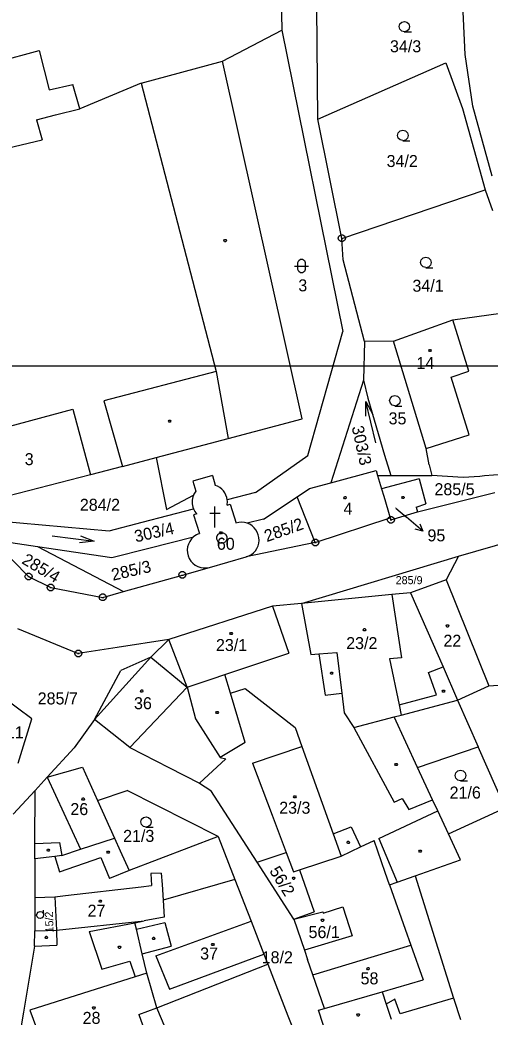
# Model space of a CAD drawing. Extents: x -780000 to -777378, y -1011169 to -1009297.
# Drawn here: x -779169.3 to -779102.6, y -1010360.1 to -1010218.8 of the extents above; entities that cross this region are included whole.
import ezdxf

# ---------------------------------------------------------------- set-up
doc = ezdxf.new("R2010")
doc.units = 0
for name, color, linetype in [('Default', 7, 'Continuous'), ('KN_HRANICE', 7, 'Continuous'), ('KN_KULTURY', 7, 'Continuous'), ('KN_PARCELY', 7, 'Continuous'), ('KN_SLUCKY', 7, 'Continuous'), ('LEGENDA', 7, 'Continuous')]:
    doc.layers.add(name, color=color, linetype=linetype)

# ---------------------------------------------------------------- blocks, each defined once
blk = doc.blocks.new('101')
at = {"layer": 'Default'}
blk.add_line((-0.05, 0), (0.05, 0), dxfattribs=at)
blk.add_lwpolyline([(0.19, 0.72), (0.53, 0.53), (0.72, 0.19), (0.72, -0.2), (0.53, -0.54), (0.19, -0.73), (-0.2, -0.73), (-0.54, -0.54), (-0.73, -0.2), (-0.73, 0.19), (-0.54, 0.53), (-0.2, 0.72), (0.19, 0.72)], dxfattribs=at)
blk = doc.blocks.new('304')
at = {"layer": 'Default'}
blk.add_lwpolyline([(0, 0), (-0.38, 0.1), (-0.65, 0.37), (-0.75, 0.74), (-0.65, 1.11), (-0.38, 1.38), (-0.01, 1.48), (0.36, 1.38), (0.63, 1.11), (0.73, 0.73), (0.63, 0.35), (0.36, 0.08), (-0.02, -0.02), (0.98, -0.02)], dxfattribs=at)
blk = doc.blocks.new('316')
at = {"layer": 'Default'}
for points in [[(-0.5, 1.5), (-0.4, 1.79), (-0.15, 1.97), (0.16, 1.97), (0.41, 1.79), (0.51, 1.5), (0.51, 0.5), (0.41, 0.21), (0.16, 0.03), (-0.15, 0.03), (-0.4, 0.21), (-0.5, 0.5), (-0.5, 1.5)], [(-1, 1), (0.27, 1), (1, 1)]]:
    blk.add_lwpolyline(points, dxfattribs=at)
blk = doc.blocks.new('NAHRADNI_SYMBOL')
at = {"layer": 'Default'}
blk.add_lwpolyline([(0.09, 0.15), (0.18, 0), (0.09, -0.15), (-0.09, -0.15), (-0.18, 0), (-0.09, 0.15), (0.09, 0.15)], dxfattribs=at)
blk = doc.blocks.new('802')
at = {"layer": 'Default'}
blk.add_line((-3, 0), (3, 0), dxfattribs=at)
blk.add_lwpolyline([(1, 0.5), (3, 0), (1, -0.5)], dxfattribs=at)
blk = doc.blocks.new('10292')
at = {"layer": 'Default'}
blk.add_line((0, 3), (0, 0), dxfattribs=at)
blk.add_lwpolyline([(-0.5, 2), (0, 3), (0.5, 2)], dxfattribs=at)
blk = doc.blocks.new('402')
at = {"layer": 'Default'}
blk.add_lwpolyline([(0.09, 0.15), (0.18, 0), (0.09, -0.15), (-0.09, -0.15), (-0.18, 0), (-0.09, 0.15), (0.09, 0.15)], dxfattribs=at)
blk = doc.blocks.new('4091')
at = {"layer": 'Default'}
for p, q in [((0, 0), (0, 3)), ((0.75, 2), (-0.75, 2))]:
    blk.add_line(p, q, dxfattribs=at)
blk = doc.blocks.new('105')
at = {"layer": 'Default'}
blk.add_line((-0.12, 0), (0.12, 0), dxfattribs=at)
blk.add_lwpolyline([(0.15, 0.48), (0.4, 0.3), (0.5, 0.01), (0.4, -0.28), (0.15, -0.46), (-0.16, -0.46), (-0.41, -0.28), (-0.51, 0.01), (-0.41, 0.3), (-0.16, 0.48), (0.15, 0.48)], dxfattribs=at)

msp = doc.modelspace()

# ---------------------------------------------------------------- linework, layer by layer
at = {"layer": 'KN_HRANICE'}
for p, q in [((-779132.76, -1010196.68), (-779132.14, -1010220.3)), ((-779106.16, -1010223.74), (-779106.91, -1010208.39)), ((-779127.06, -1010232.92), (-779127.2, -1010217)), ((-779140.53, -1010224.66), (-779132.14, -1010220.3)), ((-779132.14, -1010220.3), (-779123.49, -1010263.01)), ((-779185.42, -1010228.21), (-779166.52, -1010223.19)), ((-779166.52, -1010223.19), (-779165.11, -1010228.72)), ((-779105.07, -1010231.05), (-779106.16, -1010223.74)), ((-779152.1, -1010227.79), (-779140.53, -1010224.66)), ((-779129.26, -1010275.39), (-779140.53, -1010224.66)), ((-779127.06, -1010232.92), (-779108.9, -1010224.93)), ((-779108.9, -1010224.93), (-779106.53, -1010231.41)), ((-779165.11, -1010228.72), (-779161.77, -1010228)), ((-779160.79, -1010231.43), (-779161.77, -1010228)), ((-779152.1, -1010227.79), (-779160.79, -1010231.43)), ((-779102.33, -1010241), (-779105.07, -1010231.05)), ((-779106.53, -1010231.41), (-779103.32, -1010242.93)), ((-779123.64, -1010249.79), (-779127.06, -1010232.92)), ((-779123.64, -1010249.79), (-779103.32, -1010242.93)), ((-779103.32, -1010242.93), (-779102.28, -1010245.85)), ((-779123.44, -1010252.85), (-779123.64, -1010249.79)), ((-779120.42, -1010264.41), (-779123.44, -1010252.85)), ((-779107.93, -1010261.36), (-779101.09, -1010260.41)), ((-779116.32, -1010264.37), (-779107.93, -1010261.36)), ((-779128.47, -1010280.58), (-779123.49, -1010263.01)), ((-779120.42, -1010264.41), (-779120.56, -1010269.87)), ((-779116.32, -1010264.37), (-779120.42, -1010264.41)), ((-779111.69, -1010279.58), (-779116.32, -1010264.37)), ((-779120.56, -1010269.87), (-779125.19, -1010284.44)), ((-779120.56, -1010269.87), (-779119.96, -1010272.44)), ((-779119.96, -1010272.44), (-779117.61, -1010280.51)), ((-779139.76, -1010278.16), (-779129.26, -1010275.39)), ((-779149.94, -1010280.84), (-779139.76, -1010278.16)), ((-779135.87, -1010285.81), (-779128.47, -1010280.58)), ((-779117.61, -1010280.51), (-779116.7, -1010283.39)), ((-779111.28, -1010281.87), (-779111.69, -1010279.58)), ((-779154.7, -1010282.1), (-779159.28, -1010283.29)), ((-779154.7, -1010282.1), (-779149.94, -1010280.84)), ((-779149.94, -1010280.84), (-779148.5, -1010288.21)), ((-779111.28, -1010281.87), (-779110.91, -1010283.41)), ((-779159.28, -1010283.29), (-779177.62, -1010288.07)), ((-779141.98, -1010283.41), (-779144.76, -1010284.21)), ((-779141.98, -1010283.41), (-779141.57, -1010284.79)), ((-779125.19, -1010284.44), (-779118.78, -1010282.71)), ((-779118.78, -1010282.71), (-779118.58, -1010283.38)), ((-779118.58, -1010283.38), (-779116.7, -1010283.39)), ((-779118.58, -1010283.38), (-779118.01, -1010285.29)), ((-779116.7, -1010283.39), (-779110.91, -1010283.41)), ((-779106.44, -1010283.7), (-779110.91, -1010283.41)), ((-779144.76, -1010284.21), (-779144.33, -1010285.63)), ((-779128.24, -1010285.26), (-779125.19, -1010284.44)), ((-779112.67, -1010283.87), (-779118.01, -1010285.29)), ((-779112.67, -1010283.87), (-779111.73, -1010287.42)), ((-779148.5, -1010288.21), (-779144.67, -1010286.2)), ((-779135.87, -1010285.81), (-779139.88, -1010286.86)), ((-779129.95, -1010286.4), (-779128.24, -1010285.26)), ((-779118.01, -1010285.29), (-779117.7, -1010286.32)), ((-779117.7, -1010286.32), (-779116.78, -1010289.39)), ((-779112.94, -1010288.54), (-779101.94, -1010285.82)), ((-779139.9, -1010287.6), (-779139.45, -1010287.47)), ((-779139.45, -1010287.47), (-779138.64, -1010290.15)), ((-779134.73, -1010289.57), (-779129.95, -1010286.4)), ((-779127.4, -1010292.89), (-779129.95, -1010286.4)), ((-779113.12, -1010287.88), (-779111.73, -1010287.42)), ((-779151.93, -1010290), (-779144.67, -1010288.11)), ((-779144.21, -1010288.84), (-779144.64, -1010288.96)), ((-779144.64, -1010288.96), (-779143.83, -1010291.64)), ((-779116.69, -1010289.7), (-779112.94, -1010288.54)), ((-779113.12, -1010287.88), (-779112.94, -1010288.54)), ((-779176.23, -1010289.47), (-779156.62, -1010291.23)), ((-779156.62, -1010291.23), (-779151.93, -1010290)), ((-779134.73, -1010289.57), (-779137.06, -1010290.16)), ((-779127.4, -1010292.89), (-779116.78, -1010289.39)), ((-779116.78, -1010289.39), (-779116.69, -1010289.7)), ((-779173.19, -1010292.52), (-779168.03, -1010297.71)), ((-779173.19, -1010292.52), (-779166.79, -1010293.46)), ((-779150.97, -1010293.68), (-779144.65, -1010292.08)), ((-779127.4, -1010292.89), (-779137.19, -1010294.93)), ((-779107.13, -1010294.85), (-779097.5, -1010292.06)), ((-779166.79, -1010293.46), (-779156.22, -1010295.01)), ((-779166.79, -1010293.46), (-779154.6, -1010299.85)), ((-779156.22, -1010295.01), (-779150.97, -1010293.68)), ((-779129.38, -1010301.54), (-779107.13, -1010294.85)), ((-779107.13, -1010294.85), (-779108.85, -1010298.16)), ((-779142.38, -1010296.42), (-779137.19, -1010294.93)), ((-779154.6, -1010299.85), (-779146.24, -1010297.5)), ((-779146.24, -1010297.5), (-779142.38, -1010296.42)), ((-779168.03, -1010297.71), (-779164.89, -1010299.28)), ((-779108.85, -1010298.16), (-779113.91, -1010300.03)), ((-779164.89, -1010299.28), (-779157.51, -1010300.67)), ((-779157.51, -1010300.67), (-779154.6, -1010299.85)), ((-779116.55, -1010300.26), (-779129.38, -1010301.54)), ((-779113.91, -1010300.03), (-779116.55, -1010300.26)), ((-779113.91, -1010300.03), (-779109.3, -1010310.52)), ((-779133.45, -1010301.92), (-779148.16, -1010306.65)), ((-779129.38, -1010301.54), (-779133.45, -1010301.92)), ((-779129.38, -1010301.54), (-779128.03, -1010308.75)), ((-779169.61, -1010305.1), (-779160.99, -1010308.63)), ((-779150.7, -1010309.16), (-779148.16, -1010306.65)), ((-779145.58, -1010313.4), (-779148.16, -1010306.65)), ((-779128.03, -1010308.75), (-779126.89, -1010308.67)), ((-779126.89, -1010308.67), (-779124.34, -1010308.48)), ((-779124.34, -1010308.48), (-779123.62, -1010314.23)), ((-779150.7, -1010309.16), (-779154.94, -1010311.03)), ((-779158.7, -1010317.98), (-779154.94, -1010311.03)), ((-779142.02, -1010312.21), (-779140.22, -1010311.61)), ((-779139.43, -1010314.26), (-779140.22, -1010311.61)), ((-779109.3, -1010310.52), (-779107.24, -1010315.22)), ((-779145.58, -1010313.4), (-779142.02, -1010312.21)), ((-779107.24, -1010315.22), (-779102.83, -1010313.22)), ((-779102.83, -1010313.22), (-779096.1, -1010312.69)), ((-779145.58, -1010313.4), (-779144.39, -1010317.86)), ((-779139.43, -1010314.26), (-779137.34, -1010313.6)), ((-779137.34, -1010313.6), (-779130.26, -1010319.11)), ((-779123.62, -1010314.23), (-779123.32, -1010317.03)), ((-779167.55, -1010317.87), (-779171.61, -1010314.85)), ((-779107.24, -1010315.22), (-779104.32, -1010321.87)), ((-779123.32, -1010317.03), (-779121.94, -1010319.13)), ((-779169.49, -1010324.18), (-779167.55, -1010317.87)), ((-779158.7, -1010317.98), (-779161.56, -1010321.97)), ((-779153.68, -1010321.94), (-779158.7, -1010317.98)), ((-779144.39, -1010317.86), (-779140.88, -1010323.34)), ((-779121.94, -1010319.13), (-779116.23, -1010317.61)), ((-779112.91, -1010324.76), (-779116.23, -1010317.61)), ((-779130.26, -1010319.11), (-779129.3, -1010321.78)), ((-779165.4, -1010326.16), (-779161.56, -1010321.97)), ((-779153.68, -1010321.94), (-779148.16, -1010324.76)), ((-779129.3, -1010321.78), (-779124.85, -1010334.2)), ((-779112.91, -1010324.76), (-779104.32, -1010321.87)), ((-779100.48, -1010330.51), (-779104.32, -1010321.87)), ((-779143.8, -1010326.98), (-779140.06, -1010323.57)), ((-779140.88, -1010323.34), (-779140.06, -1010323.57)), ((-779165.4, -1010326.16), (-779160.41, -1010324.71)), ((-779160.41, -1010324.71), (-779158.26, -1010329.46)), ((-779148.16, -1010324.76), (-779143.8, -1010326.98)), ((-779110.78, -1010329.34), (-779112.91, -1010324.76)), ((-779167.12, -1010328.04), (-779165.4, -1010326.16)), ((-779143.8, -1010326.98), (-779142.22, -1010328.02)), ((-779170.22, -1010331.41), (-779167.12, -1010328.04)), ((-779167.14, -1010335.56), (-779167.12, -1010328.04)), ((-779158.26, -1010329.46), (-779154.05, -1010328.04)), ((-779141.16, -1010334.55), (-779154.05, -1010328.04)), ((-779135.65, -1010338.2), (-779142.22, -1010328.02)), ((-779158.26, -1010329.46), (-779155.86, -1010334.78)), ((-779110.04, -1010330.92), (-779110.78, -1010329.34)), ((-779108.53, -1010334.17), (-779110.04, -1010330.92)), ((-779108.53, -1010334.17), (-779100.48, -1010330.51)), ((-779124.85, -1010334.2), (-779123.73, -1010337.33)), ((-779106.82, -1010337.84), (-779108.53, -1010334.17)), ((-779167.14, -1010337.72), (-779167.14, -1010335.56)), ((-779160.66, -1010336.36), (-779155.86, -1010334.78)), ((-779155.86, -1010334.78), (-779155.05, -1010336.58)), ((-779141.16, -1010334.55), (-779153.78, -1010339.39)), ((-779141.16, -1010334.55), (-779138.79, -1010340.66)), ((-779120.99, -1010336.04), (-779119.07, -1010335.14)), ((-779117.5, -1010339.64), (-779119.07, -1010335.14)), ((-779163.3, -1010337.23), (-779164.32, -1010337.41)), ((-779163.3, -1010337.23), (-779160.66, -1010336.36)), ((-779155.05, -1010336.58), (-779153.78, -1010339.39)), ((-779135.65, -1010338.2), (-779131.51, -1010336.82)), ((-779131.51, -1010336.82), (-779130.47, -1010339.58)), ((-779123.73, -1010337.33), (-779120.99, -1010336.04)), ((-779167.14, -1010337.72), (-779167.15, -1010343.18)), ((-779164.32, -1010337.41), (-779167.14, -1010337.72)), ((-779130.45, -1010346.25), (-779135.65, -1010338.2)), ((-779129.62, -1010339.3), (-779123.73, -1010337.33)), ((-779113.27, -1010340.13), (-779106.82, -1010337.84)), ((-779130.47, -1010339.58), (-779129.62, -1010339.3)), ((-779129.62, -1010339.3), (-779127.57, -1010345.23)), ((-779116.88, -1010341.42), (-779117.5, -1010339.64)), ((-779138.79, -1010340.66), (-779148.98, -1010343.57)), ((-779138.79, -1010340.66), (-779136.5, -1010346.55)), ((-779116.88, -1010341.42), (-779115.81, -1010341.04)), ((-779116.88, -1010341.42), (-779114.67, -1010347.67)), ((-779115.81, -1010341.04), (-779113.27, -1010340.13)), ((-779113.27, -1010340.13), (-779107.81, -1010357.49)), ((-779167.15, -1010343.18), (-779167.16, -1010347.93)), ((-779167.15, -1010343.18), (-779164.31, -1010343.12)), ((-779164.31, -1010343.12), (-779164.08, -1010347.83)), ((-779148.98, -1010343.57), (-779148.82, -1010345.98)), ((-779130.45, -1010346.25), (-779127.57, -1010345.23)), ((-779164.08, -1010347.83), (-779151.66, -1010346.5)), ((-779152.96, -1010346.81), (-779151.66, -1010346.5)), ((-779152.75, -1010347.71), (-779152.96, -1010346.81)), ((-779148.82, -1010345.98), (-779151.66, -1010346.5)), ((-779136.5, -1010346.55), (-779134.69, -1010351.21)), ((-779130.45, -1010346.25), (-779128.94, -1010350.68)), ((-779167.17, -1010350.08), (-779167.16, -1010347.93)), ((-779167.16, -1010347.93), (-779164.08, -1010347.83)), ((-779151.93, -1010351.2), (-779152.75, -1010347.71)), ((-779114.67, -1010347.67), (-779113.87, -1010349.95)), ((-779127.75, -1010354.15), (-779113.87, -1010349.95)), ((-779167.17, -1010350.08), (-779168.77, -1010359.47)), ((-779151.29, -1010353.93), (-779151.93, -1010351.2)), ((-779134.69, -1010351.21), (-779134.14, -1010352.63)), ((-779128.94, -1010350.68), (-779128.49, -1010351.99)), ((-779149.85, -1010358.82), (-779134.14, -1010352.63)), ((-779134.14, -1010352.63), (-779131.3, -1010359.95)), ((-779127.75, -1010354.15), (-779128.49, -1010351.99)), ((-779149.85, -1010358.82), (-779151.29, -1010353.93)), ((-779126.12, -1010358.95), (-779127.75, -1010354.15)), ((-779126.12, -1010358.95), (-779117.94, -1010356.58)), ((-779117.94, -1010356.58), (-779117.35, -1010358.34)), ((-779117.35, -1010358.34), (-779116.64, -1010360.46)), ((-779107.81, -1010357.49), (-779107.71, -1010357.68)), ((-779106.8, -1010360.53), (-779107.71, -1010357.68)), ((-779168.77, -1010359.47), (-779169.76, -1010365.24)), ((-779148.14, -1010362.87), (-779149.85, -1010358.82)), ((-779126.93, -1010359.19), (-779126.12, -1010358.95)), ((-779124.81, -1010365.65), (-779126.93, -1010359.19)), ((-779131.3, -1010359.95), (-779128.72, -1010366.32))]:
    msp.add_line(p, q, dxfattribs=at)
for points in [[(-779097.04, -1010282.96), (-779103.42, -1010283.46), (-779104.11, -1010283.52), (-779106.44, -1010283.7)], [(-779148.16, -1010306.65), (-779155.46, -1010307.78), (-779160.99, -1010308.63)], [(-779107.81, -1010357.49), (-779115.4, -1010359.69), (-779116.13, -1010357.63), (-779117.35, -1010358.34)]]:
    msp.add_lwpolyline(points, dxfattribs=at)
for centre, radius, start, end in [((-779142.38, -1010287.18), 2.52, 7.2029, 71.2552), ((-779142.41, -1010287.15), 2.45, 157.0664, 202.9336), ((-779142.11, -1010287.34), 2.8, 142.3745, 155.9941), ((-779142.16, -1010287.17), 2.3, 349.1876, 7.7161), ((-779142.3, -1010287.13), 2.56, 202.5278, 221.9053), ((-779137.87, -1010292.59), 2.56, 71.6556, 107.6192), ((-779137.87, -1010292.52), 2.5, 285.7463, 71.1314), ((-779142.99, -1010294.19), 2.68, 108.2322, 128.2025), ((-779143.03, -1010294), 2.51, 130.2372, 284.9856)]:
    msp.add_arc(centre, radius, start, end, dxfattribs=at)
at = {"layer": 'KN_PARCELY'}
msp.add_line((-779116, -1010288.01), (-779114.46, -1010289.32), dxfattribs=at)
at = {"layer": 'KN_SLUCKY'}
for p, q in [((-779152.1, -1010227.79), (-779141.46, -1010268.66)), ((-779166.93, -1010233.01), (-779164.21, -1010232.28)), ((-779164.21, -1010232.28), (-779160.79, -1010231.43)), ((-779166.93, -1010233.01), (-779166.12, -1010235.81)), ((-779171.09, -1010237.01), (-779166.12, -1010235.81)), ((-779105.66, -1010268.59), (-779107.93, -1010261.36)), ((-779141.46, -1010268.66), (-779157.38, -1010272.82)), ((-779141.46, -1010268.66), (-779139.76, -1010278.16)), ((-779108.14, -1010269.47), (-779105.66, -1010268.59)), ((-779105.62, -1010277.63), (-779108.14, -1010269.47)), ((-779157.38, -1010272.82), (-779154.7, -1010282.1)), ((-779178.75, -1010278.56), (-779161.78, -1010273.99)), ((-779161.78, -1010273.99), (-779159.28, -1010283.29)), ((-779111.69, -1010279.58), (-779105.62, -1010277.63)), ((-779108.85, -1010298.16), (-779102.83, -1010313.22)), ((-779116.55, -1010300.26), (-779115.17, -1010309.24)), ((-779133.45, -1010301.92), (-779131.16, -1010308.58)), ((-779140.22, -1010311.61), (-779131.16, -1010308.58)), ((-779126.89, -1010308.67), (-779126, -1010314.52)), ((-779158.7, -1010317.98), (-779150.7, -1010309.16)), ((-779150.7, -1010309.16), (-779145.58, -1010313.4)), ((-779115.17, -1010309.24), (-779116.88, -1010309.36)), ((-779116.88, -1010309.36), (-779115.53, -1010315.91)), ((-779111.38, -1010311.33), (-779109.3, -1010310.52)), ((-779110.21, -1010314.47), (-779111.38, -1010311.33)), ((-779153.68, -1010321.94), (-779145.58, -1010313.4)), ((-779137.35, -1010321.23), (-779139.43, -1010314.26)), ((-779126, -1010314.52), (-779123.62, -1010314.23)), ((-779115.53, -1010315.91), (-779110.21, -1010314.47)), ((-779115.53, -1010315.91), (-779115.23, -1010317.34)), ((-779115.23, -1010317.34), (-779107.24, -1010315.22)), ((-779116.23, -1010317.61), (-779115.23, -1010317.34)), ((-779121.94, -1010319.13), (-779116.22, -1010329.71)), ((-779137.35, -1010321.23), (-779140.88, -1010323.34)), ((-779136.29, -1010324.15), (-779129.3, -1010321.78)), ((-779136.29, -1010324.15), (-779133.52, -1010331.51)), ((-779165.4, -1010326.16), (-779160.66, -1010336.36)), ((-779116.22, -1010329.71), (-779115.11, -1010329.15)), ((-779115.11, -1010329.15), (-779114.16, -1010330.74)), ((-779114.16, -1010330.74), (-779110.78, -1010329.34)), ((-779133.52, -1010331.51), (-779131.51, -1010336.82)), ((-779118.38, -1010334.82), (-779110.04, -1010330.92)), ((-779124.85, -1010334.2), (-779122.33, -1010333.18)), ((-779122.33, -1010333.18), (-779120.99, -1010336.04)), ((-779167.14, -1010335.56), (-779163.63, -1010335.4)), ((-779163.63, -1010335.4), (-779163.3, -1010337.23)), ((-779118.38, -1010334.82), (-779115.81, -1010341.04)), ((-779164.32, -1010337.41), (-779163.63, -1010339.56)), ((-779163.63, -1010339.56), (-779157.78, -1010337.53)), ((-779157.78, -1010337.53), (-779156.56, -1010340.49)), ((-779153.78, -1010339.39), (-779156.56, -1010340.49)), ((-779149.23, -1010339.75), (-779150.73, -1010339.81)), ((-779150.73, -1010339.81), (-779150.61, -1010341.52)), ((-779149.23, -1010339.75), (-779149.12, -1010341.37)), ((-779149.12, -1010341.37), (-779148.98, -1010343.57)), ((-779162.78, -1010342.94), (-779152.1, -1010341.68)), ((-779152.1, -1010341.68), (-779150.61, -1010341.52)), ((-779164.31, -1010343.12), (-779162.78, -1010342.94)), ((-779130.45, -1010346.25), (-779126.34, -1010345.23)), ((-779126.34, -1010345.23), (-779126.27, -1010345.4)), ((-779126.27, -1010345.4), (-779123.51, -1010344.52)), ((-779123.51, -1010344.52), (-779122.2, -1010348.62)), ((-779159.47, -1010348.01), (-779152.96, -1010346.81)), ((-779152.75, -1010347.71), (-779148.71, -1010346.75)), ((-779149.98, -1010351.45), (-779136.5, -1010346.55)), ((-779148.71, -1010346.75), (-779147.85, -1010350.1)), ((-779164.08, -1010347.83), (-779164.04, -1010349.95)), ((-779159.47, -1010348.01), (-779157.66, -1010353.36)), ((-779167.17, -1010350.08), (-779164.04, -1010349.95)), ((-779122.2, -1010348.62), (-779128.94, -1010350.68)), ((-779113.87, -1010349.95), (-779112.12, -1010354.89)), ((-779151.93, -1010351.2), (-779147.85, -1010350.1)), ((-779148.04, -1010356.21), (-779134.69, -1010351.21)), ((-779157.66, -1010353.36), (-779153.67, -1010352.23)), ((-779153.67, -1010352.23), (-779152.93, -1010354.43)), ((-779149.98, -1010351.45), (-779148.04, -1010356.21)), ((-779151.29, -1010353.93), (-779152.93, -1010354.43)), ((-779152.93, -1010354.43), (-779167.87, -1010359.19)), ((-779117.94, -1010356.58), (-779112.12, -1010354.89)), ((-779167.87, -1010359.19), (-779166.01, -1010364.05)), ((-779152.41, -1010359.76), (-779149.85, -1010358.82)), ((-779152.41, -1010359.76), (-779150.92, -1010363.88))]:
    msp.add_line(p, q, dxfattribs=at)
at = {"layer": 'LEGENDA'}
msp.add_lwpolyline([(-779530.66, -1010687.91), (-778936.66, -1010687.91), (-778936.66, -1010267.91), (-779530.66, -1010267.91)], close=True, dxfattribs=at)

# ---------------------------------------------------------------- block references
at = {"layer": 'KN_KULTURY'}
for name, p in [('304', (-779114.77, -1010220.52)), ('304', (-779114.99, -1010235.94)), ('402', (-779140.18, -1010250.11)), ('304', (-779111.73, -1010253.93)), ('316', (-779129.36, -1010254.72)), ('402', (-779111.15, -1010265.67)), ('304', (-779116.12, -1010273.53)), ('402', (-779148.04, -1010275.71)), ('402', (-779123.19, -1010286.54)), ('NAHRADNI_SYMBOL', (-779114.97, -1010286.53)), ('4091', (-779141.62, -1010290.77)), ('402', (-779140.79, -1010291.53)), ('402', (-779108.68, -1010304.72)), ('402', (-779139.32, -1010305.78)), ('402', (-779120.43, -1010305.25)), ('402', (-779125.09, -1010311.42)), ('402', (-779152, -1010313.94)), ('402', (-779109.24, -1010313.97)), ('402', (-779141.32, -1010316.99)), ('402', (-779115.94, -1010324.35)), ('304', (-779106.82, -1010326.65)), ('402', (-779130.3, -1010328.92)), ('402', (-779160.31, -1010329.25)), ('304', (-779151.38, -1010333.23)), ('402', (-779122.73, -1010335.39)), ('402', (-779165.24, -1010336.5)), ('402', (-779156.75, -1010336.78)), ('402', (-779112.55, -1010336.62)), ('402', (-779130.47, -1010340.48)), ('402', (-779157.87, -1010343.72)), ('402', (-779126.38, -1010346.43)), ('402', (-779165.52, -1010348.85)), ('402', (-779150.31, -1010348.99)), ('402', (-779141.92, -1010349.85)), ('402', (-779155.14, -1010350.26)), ('402', (-779119.93, -1010353.29)), ('402', (-779158.8, -1010358.86)), ('402', (-779121.32, -1010359.85))]:
    msp.add_blockref(name, p, dxfattribs=at)
for p, rotation in [((-779119.52, -1010275.84), 103.648065), ((-779161.73, -1010292.32), -6.9434070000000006)]:
    msp.add_blockref('802', p, dxfattribs=dict(at, rotation=rotation))
at = {"layer": 'KN_KULTURY', "xscale": 0.67, "yscale": 0.67, "rotation": 92.87645899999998}
msp.add_blockref('304', (-779165.9, -1010345.65), dxfattribs=at)
at = {"layer": 'KN_PARCELY'}
for name, p in [('105', (-779123.64, -1010249.79)), ('105', (-779116.69, -1010289.7)), ('101', (-779140.64, -1010292.24)), ('105', (-779127.4, -1010292.89)), ('105', (-779168.03, -1010297.71)), ('105', (-779146.24, -1010297.5)), ('105', (-779164.89, -1010299.28)), ('105', (-779157.51, -1010300.67)), ('105', (-779160.99, -1010308.63))]:
    msp.add_blockref(name, p, dxfattribs=at)
at = {"layer": 'KN_PARCELY', "rotation": -130.41581100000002}
msp.add_blockref('10292', (-779114.46, -1010289.32), dxfattribs=at)

# ---------------------------------------------------------------- texts
at = {"layer": 'KN_PARCELY'}
for s, height, p in [('34/3', 1.7, (-779116.82, -1010223.42)), ('34/2', 1.7, (-779117.3, -1010239.68)), ('3', 1.7, (-779129.81, -1010257.3)), ('34/1', 1.7, (-779113.64, -1010257.35)), ('14', 1.7, (-779113.08, -1010268.31)), ('35', 1.7, (-779117.02, -1010276.15)), ('3', 1.7, (-779168.58, -1010281.93)), ('285/5', 1.7, (-779110.52, -1010286.19)), ('284/2', 1.7, (-779160.77, -1010288.4)), ('4', 1.7, (-779123.41, -1010288.93)), ('95', 0.1, (-779116.1, -1010288.01)), ('95', 1.7, (-779111.51, -1010292.73)), ('60', 1.7, (-779141.35, -1010293.92)), ('285/9', 1.14, (-779116.02, -1010298.8)), ('22', 1.7, (-779109.25, -1010307.66)), ('23/1', 1.7, (-779141.48, -1010308.27)), ('23/2', 1.7, (-779123.03, -1010308)), ('285/7', 1.7, (-779166.74, -1010315.84)), ('36', 1.7, (-779153.09, -1010316.52)), ('11', 1.7, (-779171.25, -1010320.64)), ('21/6', 1.7, (-779108.37, -1010329.18)), ('26', 1.7, (-779162.11, -1010331.52)), ('23/3', 1.7, (-779132.52, -1010331.33)), ('21/3', 1.7, (-779154.64, -1010335.32)), ('27', 1.7, (-779159.67, -1010345.92)), ('56/1', 1.7, (-779128.36, -1010348.95)), ('37', 1.7, (-779143.72, -1010351.99)), ('18/2', 1.7, (-779135, -1010352.52)), ('58', 1.7, (-779120.99, -1010355.51)), ('28', 1.7, (-779160.37, -1010361.11))]:
    msp.add_text(s, height=height, dxfattribs=at).set_placement(p)
for s, height, rotation, p in [('303/3', 1.7, 282.296, (-779122.26, -1010276.53)), ('303/4', 1.7, 12.72, (-779152.83, -1010292.89)), ('285/2', 1.7, 19.595, (-779134.28, -1010292.85)), ('285/4', 1.7, 329.164, (-779169.12, -1010295.78)), ('285/3', 1.7, 13.063, (-779156.08, -1010298.32)), ('56/2', 1.7, 301.662, (-779133.97, -1010339.43)), ('15/2', 1.14, 91.616, (-779164.49, -1010348.14))]:
    msp.add_text(s, height=height, rotation=rotation, dxfattribs=at).set_placement(p)

doc.saveas('drawing.dxf')
